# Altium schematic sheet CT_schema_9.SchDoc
size 274 x 160 mm
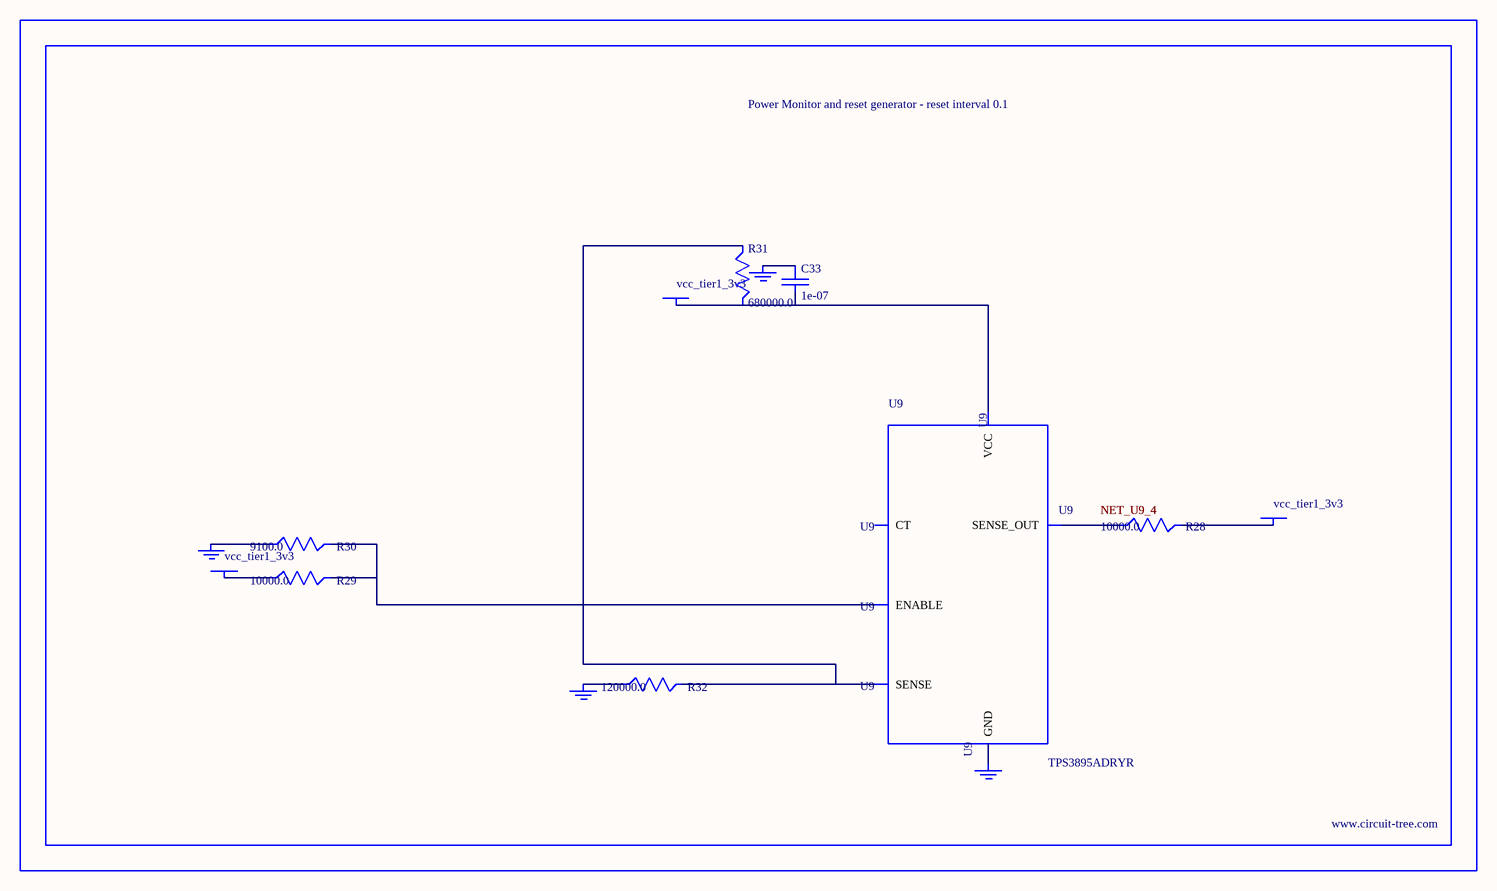
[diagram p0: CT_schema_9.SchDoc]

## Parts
BORDER8  (no value)
C33  1e-07  [C0402]
GND_INSTANCE_8_0  (no value)
GND_INSTANCE_8_1  (no value)
GND_INSTANCE_8_2  (no value)
GND_INSTANCE_8_3  (no value)
POWER_INSTANCE_8_0  vcc_tier1_3v3
POWER_INSTANCE_8_1  vcc_tier1_3v3
POWER_INSTANCE_8_2  vcc_tier1_3v3
R28  10000.0  [R0603]
R29  10000.0  [R0603]
R30  9100.0  [R0603]
R31  680000.0  [R0603]
R32  120000.0  [R0603]
U9  TPS3895ADRYR  [SON-6]

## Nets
NetC33_1: C33.1 GND_INSTANCE_8_2.0(GND)
NetC33_2: C33.2 POWER_INSTANCE_8_2.0(PWR) R31.2 U9.6(VCC)
NetGND_INSTANCE_8_0_0: GND_INSTANCE_8_0.0(GND) R30.1
NetGND_INSTANCE_8_1_0: GND_INSTANCE_8_1.0(GND) R32.1
NetGND_INSTANCE_8_3_0: GND_INSTANCE_8_3.0(GND) U9.2(GND)
NetPOWER_INSTANCE_8_0_0: POWER_INSTANCE_8_0.0(PWR) R29.1
NetPOWER_INSTANCE_8_1_0: POWER_INSTANCE_8_1.0(PWR) R28.2
NetR28_1: R28.1 U9.4(SENSE_OUT)
NetR29_2: R29.2 R30.2 U9.1(ENABLE)
NetR31_1: R31.1 R32.2 U9.3(SENSE)

Not connected (* = marked no-connect by the designer): U9 5(CT)

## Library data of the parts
BORDER8 = BORDER_PAGE8
C33 = C0402C104K3RACTU
GND_INSTANCE_8_0-GND_INSTANCE_8_3 = GND
POWER_INSTANCE_8_0-POWER_INSTANCE_8_2 = PWR
R28 R29 = RC0603JR-0710KL
R30 = RC0603JR-079K1L
R31 = RC0603JR-07680KL
R32 = RC0603JR-07120KL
